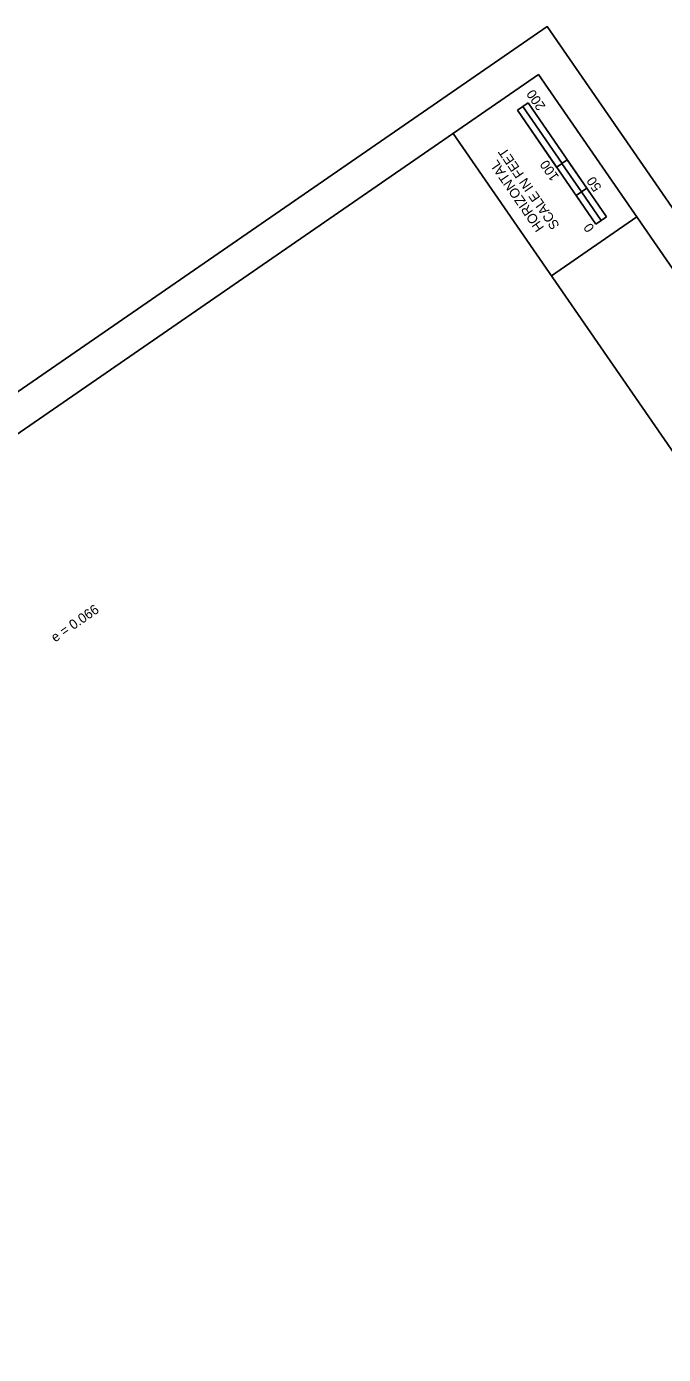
# Model space of a CAD drawing. Extents: x 2200598 to 2206607, y 633643 to 637565.
# Drawn here: x 2202644 to 2203565, y 635464 to 637385 of the extents above; entities that cross this region are included whole.
import ezdxf

# ---------------------------------------------------------------- set-up
doc = ezdxf.new("R2010")
doc.units = 0
for name, color, linetype in [('_CIVIL_CONSTRUCTION', 7, 'Continuous'), ('RW_X_CL_100_Bearings', 7, 'Continuous'), ('RW_X_CL_100_Cardinal_Points', 7, 'Continuous'), ('RW_X_CL_100_Curve_Data', 7, 'Continuous')]:
    doc.layers.add(name, color=color, linetype=linetype)

msp = doc.modelspace()

# ---------------------------------------------------------------- linework, layer by layer
at = {"layer": 'RW_X_CL_100_Bearings'}
msp.add_lwpolyline([(2201848.1, 633642.8), (2204646.3, 635574.1), (2203396.7, 637384.7), (2200598.4, 635453.4)], close=True, dxfattribs=at)
at = {"layer": 'RW_X_CL_100_Cardinal_Points'}
for p, q in [((2203368.8, 637274.3), (2203353.4, 637263.7)), ((2203353.4, 637263.7), (2203361.1, 637269)), ((2203467, 637099.1), (2203353.4, 637263.7)), ((2203410.2, 637181.4), (2203353.4, 637263.7)), ((2203361.1, 637269), (2203418, 637186.7)), ((2203361.1, 637269), (2203361.1, 637269)), ((2203368.8, 637274.3), (2203482.4, 637109.7)), ((2203418, 637186.7), (2203410.2, 637181.4)), ((2203425.6, 637192), (2203417.9, 637186.7)), ((2203417.9, 637186.7), (2203446.3, 637145.5)), ((2203454, 637150.8), (2203425.6, 637192)), ((2203446.3, 637145.5), (2203438.6, 637140.2)), ((2203446.3, 637145.5), (2203454, 637150.8)), ((2203474.7, 637104.4), (2203446.3, 637145.5)), ((2203438.6, 637140.2), (2203467, 637099.1)), ((2203482.4, 637109.7), (2203467, 637099.1)), ((2203467, 637099.1), (2203474.7, 637104.4))]:
    msp.add_line(p, q, dxfattribs=at)
at = {"layer": 'RW_X_CL_100_Curve_Data'}
for p, q in [((2204453.3, 635501.6), (2203260.5, 637229.9)), ((2203402.5, 637024.2), (2203525.9, 637109.4))]:
    msp.add_line(p, q, dxfattribs=at)
msp.add_lwpolyline([(2200750.3, 635497.4), (2203383.9, 637315.1), (2204576.8, 635586.8), (2201943.2, 633769.1)], close=True, dxfattribs=at)

# ---------------------------------------------------------------- texts
at = {"layer": '_CIVIL_CONSTRUCTION'}
msp.add_text('e = 0.066', height=14, rotation=34.613, dxfattribs=at).set_placement((2202685.3, 636493.7))
at = {"layer": 'RW_X_CL_100_Cardinal_Points'}
for s, p in [('200', (2203394.8, 637269.4)), ('SCALE IN FEET', (2203415, 637097.1)), ('HORIZONTAL', (2203392.6, 637093.9)), ('100', (2203414.2, 637167.4)), ('50', (2203475.8, 637152.1)), ('0', (2203465.4, 637093.3))]:
    msp.add_text(s, height=14, rotation=124.613, dxfattribs=at).set_placement(p)

doc.saveas('drawing.dxf')
